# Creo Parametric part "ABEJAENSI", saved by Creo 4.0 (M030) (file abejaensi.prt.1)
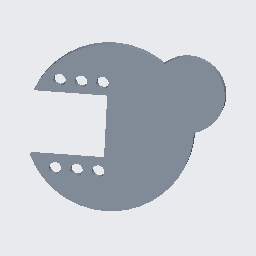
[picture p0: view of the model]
Units: millimeter Newton Second (mmNs); MM, TONNE, SECS

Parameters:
  MODELED_BY = "AJ"

Created from: MMNS_PART_SOLID.PRT

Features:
  1. datum plane "RIGHT"
  2. datum plane "TOP"
  3. datum plane "FRONT"
  4. coordinate system
  5. sketch "Sketch 1"
  6. extrusion "Extrude 1"
  7. pattern "Pattern 1"
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
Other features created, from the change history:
  hole "Hole 1"
  hole "Hole 1 [2]"
  hole "Hole 1 [3]"
  mirror "Mirror 1"
  pattern "Pattern 1 (2)"
  hole "Hole 1 (2) [1]"
  hole "Hole 1 (2) [2]"
  hole "Hole 1 (2) [3]"

Surfaces: 9 cylinder, 5 plane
